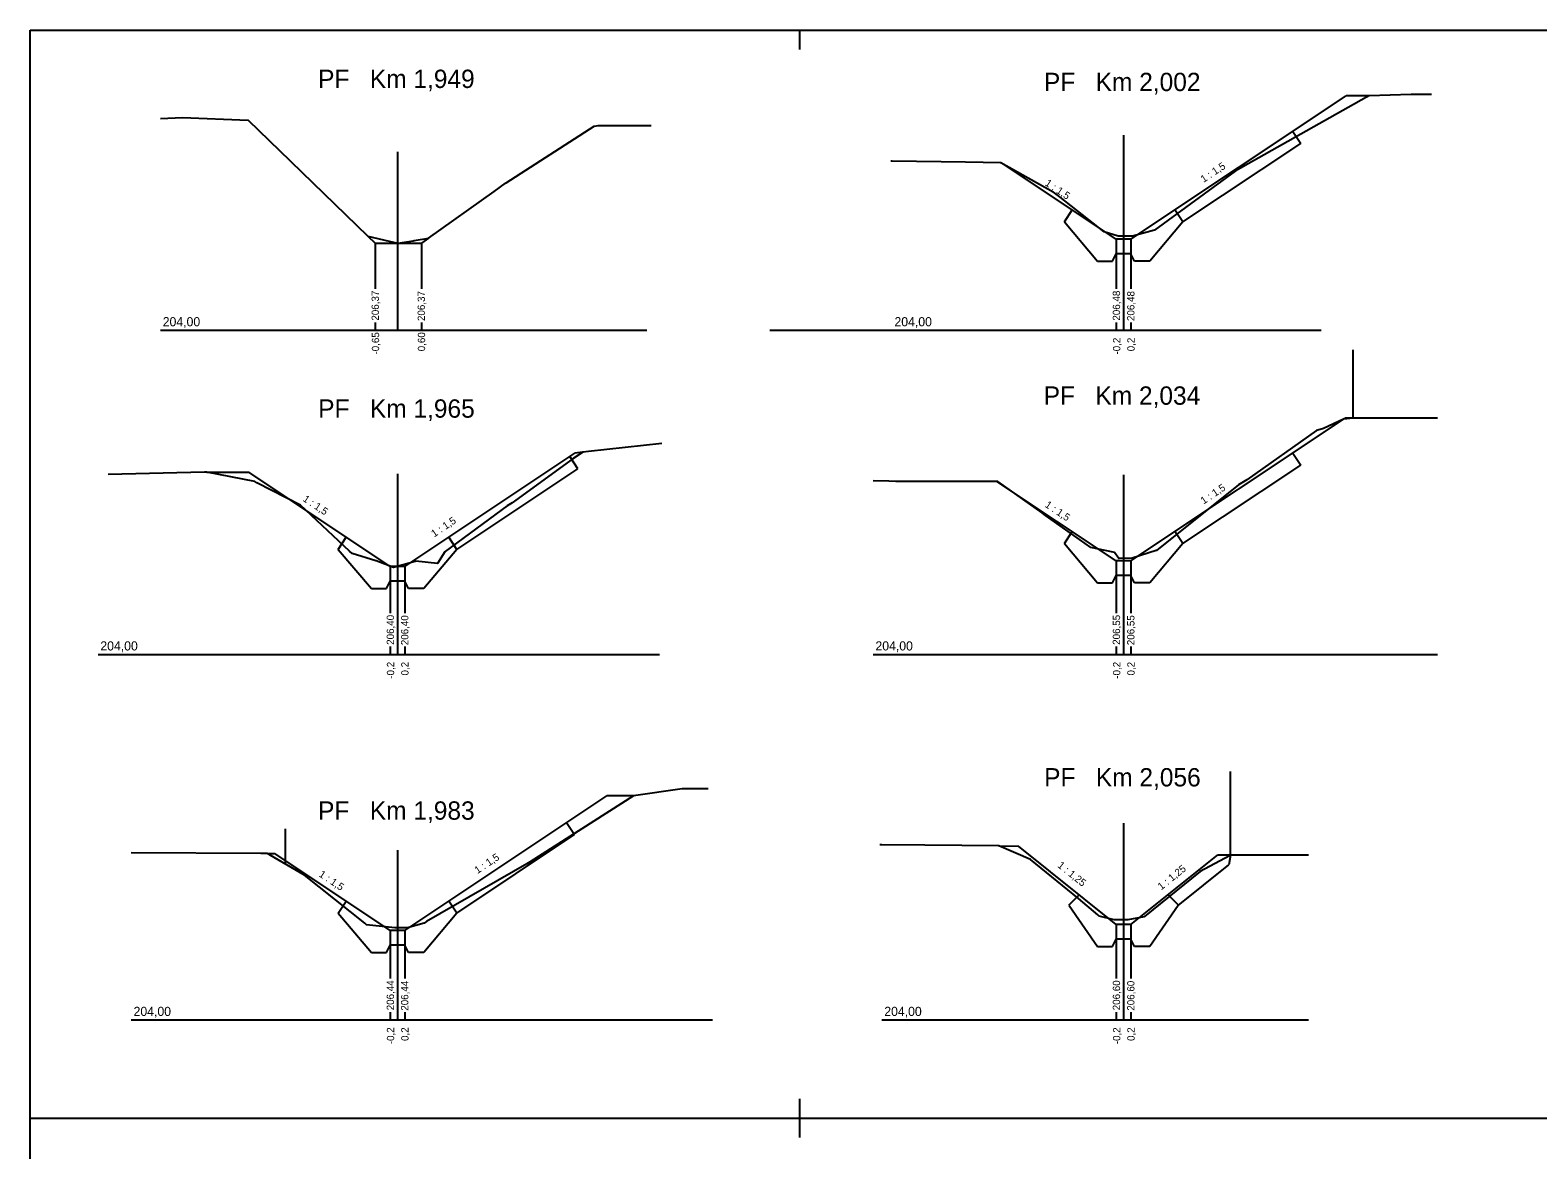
# Model space of a CAD drawing. Extents: x -547174 to -543113, y -1125006 to -1123643.
# Drawn here: x -547152.27 to -547111.11, y -1123875.1 to -1123844.54 of the extents above; entities that cross this region are included whole.
import ezdxf

# ---------------------------------------------------------------- set-up
doc = ezdxf.new("R2010")
doc.units = 0
for name, color, linetype in [('Default', 7, 'Continuous'), ('Profile', 7, 'Continuous'), ('PROFILY NÁVRH', 7, 'Continuous'), ('Section', 7, 'Continuous'), ('STANIČENÍ', 7, 'Continuous')]:
    doc.layers.add(name, color=color, linetype=linetype)

msp = doc.modelspace()

# ---------------------------------------------------------------- linework, layer by layer
at = {"layer": 'Default'}
for points in [[(-547114.012, -1123846.293), (-547114.571, -1123846.296), (-547114.574, -1123846.292), (-547115.721, -1123846.332), (-547115.75, -1123846.34), (-547115.752, -1123846.343), (-547115.789, -1123846.369), (-547119.372, -1123848.383), (-547121.574, -1123849.994), (-547121.578, -1123849.997), (-547122.174, -1123850.157), (-547122.175, -1123850.157), (-547122.416, -1123850.157), (-547122.416, -1123850.158), (-547122.417, -1123850.157), (-547122.573, -1123850.157), (-547122.574, -1123850.157), (-547122.574, -1123850.157), (-547122.952, -1123850.046), (-547124.157, -1123849.1), (-547124.337, -1123848.958), (-547124.339, -1123848.957), (-547124.34, -1123848.956), (-547125.777, -1123848.157), (-547126.739, -1123848.144), (-547128.74, -1123848.114), (-547128.776, -1123848.116)], [(-547148.717, -1123846.952), (-547148.117, -1123846.924), (-547146.32, -1123846.999), (-547145.178, -1123848.103), (-547145.175, -1123848.107), (-547145.168, -1123848.114), (-547143.058, -1123850.16), (-547142.47, -1123850.296), (-547142.467, -1123850.296), (-547142.238, -1123850.349), (-547142.236, -1123850.349), (-547141.82, -1123850.289), (-547141.788, -1123850.279), (-547141.396, -1123850.219), (-547139.605, -1123848.941), (-547139.291, -1123848.717), (-547139.277, -1123848.708), (-547136.874, -1123847.16), (-547136.77, -1123847.14), (-547135.32, -1123847.143)], [(-547113.853, -1123855.128), (-547114.6, -1123855.128), (-547116.156, -1123855.13), (-547116.418, -1123855.154), (-547116.963, -1123855.415), (-547116.988, -1123855.425), (-547117.151, -1123855.47), (-547117.152, -1123855.47), (-547119.059, -1123856.814), (-547119.197, -1123856.891), (-547119.282, -1123856.954), (-547121.519, -1123858.741), (-547121.536, -1123858.745), (-547122.189, -1123858.949), (-547122.197, -1123858.949), (-547122.542, -1123858.959), (-547122.548, -1123858.959), (-547122.67, -1123858.795), (-547122.705, -1123858.787), (-547123.312, -1123858.663), (-547124.553, -1123857.784), (-547124.587, -1123857.757), (-547124.641, -1123857.714), (-547125.859, -1123856.856), (-547125.859, -1123856.856), (-547125.984, -1123856.856), (-547128.337, -1123856.86), (-547128.338, -1123856.86), (-547128.639, -1123856.856), (-547128.831, -1123856.853), (-547129.259, -1123856.84)], [(-547135.025, -1123855.821), (-547137.03, -1123856.043), (-547137.182, -1123856.06), (-547137.451, -1123856.232), (-547139.111, -1123857.443), (-547139.246, -1123857.523), (-547140.942, -1123858.768), (-547140.954, -1123858.783), (-547141.151, -1123859.099), (-547141.74, -1123859.032), (-547141.765, -1123859.041), (-547142.349, -1123859.207), (-547142.352, -1123859.207), (-547142.355, -1123859.207), (-547142.829, -1123859.029), (-547142.836, -1123859.028), (-547143.48, -1123858.828), (-547143.481, -1123858.827), (-547143.553, -1123858.763), (-547144.893, -1123857.509), (-547146.084, -1123856.894), (-547146.141, -1123856.858), (-547147.452, -1123856.604), (-547147.509, -1123856.604), (-547150.146, -1123856.67)], [(-547133.762, -1123865.246), (-547134.072, -1123865.245), (-547134.465, -1123865.245), (-547134.467, -1123865.245), (-547134.47, -1123865.245), (-547135.799, -1123865.441), (-547138.626, -1123867.242), (-547138.717, -1123867.293), (-547141.456, -1123868.869), (-547141.516, -1123868.913), (-547141.968, -1123869.041), (-547141.978, -1123869.044), (-547141.983, -1123869.044), (-547142.14, -1123869.044), (-547142.308, -1123869.044), (-547142.311, -1123869.044), (-547142.319, -1123869.042), (-547143.086, -1123868.962), (-547143.139, -1123868.921), (-547144.781, -1123867.607), (-547145.717, -1123867.061), (-547145.801, -1123867.013), (-547145.979, -1123867.011), (-547149.513, -1123866.992)], [(-547117.373, -1123867.058), (-547119.462, -1123867.063), (-547119.505, -1123867.063), (-547119.528, -1123867.078), (-547120.332, -1123867.504), (-547121.851, -1123868.739), (-547121.859, -1123868.745), (-547121.861, -1123868.745), (-547122.306, -1123868.825), (-547122.504, -1123868.825), (-547122.506, -1123868.825), (-547122.508, -1123868.825), (-547122.673, -1123868.825), (-547122.677, -1123868.825), (-547123.084, -1123868.725), (-547123.129, -1123868.689), (-547123.655, -1123868.241), (-547124.96, -1123867.18), (-547125.826, -1123866.805), (-547127.849, -1123866.786), (-547129.019, -1123866.78), (-547129.077, -1123866.778)]]:
    msp.add_lwpolyline(points, dxfattribs=at)
at = {"layer": 'Profile'}
for p, q in [((-547152.272, -1123844.537), (-547131.272, -1123844.537)), ((-547152.272, -1123874.237), (-547152.272, -1123844.537)), ((-547131.272, -1123844.537), (-547110.272, -1123844.537)), ((-547131.272, -1123844.537), (-547131.272, -1123845.065)), ((-547131.272, -1123873.709), (-547131.272, -1123874.237)), ((-547152.272, -1123874.237), (-547138.818, -1123874.237)), ((-547152.272, -1123874.237), (-547131.272, -1123874.237)), ((-547152.272, -1123903.937), (-547152.272, -1123874.237)), ((-547131.272, -1123874.237), (-547115.303, -1123874.237)), ((-547131.272, -1123874.237), (-547110.272, -1123874.237)), ((-547131.272, -1123874.237), (-547131.272, -1123874.765))]:
    msp.add_line(p, q, dxfattribs=at)
at = {"layer": 'PROFILY NÁVRH'}
for p, q in [((-547122.221, -1123850.247), (-547116.348, -1123846.332)), ((-547115.721, -1123846.332), (-547116.348, -1123846.332)), ((-547117.804, -1123847.302), (-547117.586, -1123847.629)), ((-547120.803, -1123849.773), (-547117.586, -1123847.629)), ((-547125.777, -1123848.157), (-547125.755, -1123848.158)), ((-547122.621, -1123850.247), (-547125.755, -1123848.158)), ((-547124.038, -1123849.773), (-547123.821, -1123849.447)), ((-547120.803, -1123849.773), (-547121.021, -1123849.447)), ((-547124.038, -1123849.773), (-547123.136, -1123850.847)), ((-547120.803, -1123849.773), (-547121.706, -1123850.847)), ((-547143.058, -1123850.16), (-547142.854, -1123850.357)), ((-547141.396, -1123850.219), (-547141.59, -1123850.357)), ((-547122.221, -1123850.247), (-547122.621, -1123850.247)), ((-547122.621, -1123850.247), (-547122.621, -1123851.603)), ((-547122.221, -1123850.247), (-547122.221, -1123851.603)), ((-547142.854, -1123850.357), (-547141.59, -1123850.357)), ((-547142.854, -1123850.357), (-547142.854, -1123851.603)), ((-547141.59, -1123850.357), (-547141.59, -1123851.603)), ((-547122.721, -1123850.847), (-547122.621, -1123850.647)), ((-547122.221, -1123850.647), (-547122.621, -1123850.647)), ((-547122.121, -1123850.847), (-547122.221, -1123850.647)), ((-547123.136, -1123850.847), (-547122.721, -1123850.847)), ((-547121.706, -1123850.847), (-547122.121, -1123850.847)), ((-547142.854, -1123852.515), (-547142.854, -1123852.727)), ((-547141.59, -1123852.515), (-547141.59, -1123852.727)), ((-547122.621, -1123852.515), (-547122.621, -1123852.727)), ((-547122.221, -1123852.515), (-547122.221, -1123852.727)), ((-547122.221, -1123859.028), (-547116.374, -1123855.13)), ((-547116.156, -1123855.13), (-547116.374, -1123855.13)), ((-547142.043, -1123859.178), (-547137.404, -1123856.085)), ((-547137.182, -1123856.06), (-547137.404, -1123856.085)), ((-547117.804, -1123856.083), (-547117.586, -1123856.409)), ((-547140.621, -1123858.711), (-547137.321, -1123856.511)), ((-547137.321, -1123856.511), (-547137.543, -1123856.178)), ((-547120.803, -1123858.554), (-547117.586, -1123856.409)), ((-547147.452, -1123856.604), (-547146.303, -1123856.604)), ((-547142.443, -1123859.178), (-547146.303, -1123856.604)), ((-547122.621, -1123859.028), (-547125.878, -1123856.856)), ((-547143.865, -1123858.711), (-547143.643, -1123858.378)), ((-547140.621, -1123858.711), (-547140.843, -1123858.378)), ((-547124.038, -1123858.554), (-547123.821, -1123858.228)), ((-547124.038, -1123858.554), (-547123.136, -1123859.628)), ((-547120.803, -1123858.554), (-547121.706, -1123859.628)), ((-547120.803, -1123858.554), (-547121.021, -1123858.228)), ((-547143.865, -1123858.711), (-547142.958, -1123859.778)), ((-547140.621, -1123858.711), (-547141.528, -1123859.778)), ((-547142.043, -1123859.178), (-547142.443, -1123859.178)), ((-547142.443, -1123859.178), (-547142.443, -1123860.454)), ((-547142.043, -1123859.178), (-547142.043, -1123860.454)), ((-547122.221, -1123859.028), (-547122.621, -1123859.028)), ((-547122.621, -1123859.028), (-547122.621, -1123860.454)), ((-547122.221, -1123859.028), (-547122.221, -1123860.454)), ((-547142.958, -1123859.778), (-547142.543, -1123859.778)), ((-547142.543, -1123859.778), (-547142.443, -1123859.578)), ((-547142.043, -1123859.578), (-547142.443, -1123859.578)), ((-547141.943, -1123859.778), (-547142.043, -1123859.578)), ((-547141.528, -1123859.778), (-547141.943, -1123859.778)), ((-547123.136, -1123859.628), (-547122.721, -1123859.628)), ((-547122.721, -1123859.628), (-547122.621, -1123859.428)), ((-547122.221, -1123859.428), (-547122.621, -1123859.428)), ((-547122.121, -1123859.628), (-547122.221, -1123859.428)), ((-547121.706, -1123859.628), (-547122.121, -1123859.628)), ((-547142.443, -1123861.366), (-547142.443, -1123861.578)), ((-547142.043, -1123861.366), (-547142.043, -1123861.578)), ((-547122.621, -1123861.366), (-547122.621, -1123861.578)), ((-547122.221, -1123861.366), (-547122.221, -1123861.578)), ((-547142.043, -1123869.115), (-547136.531, -1123865.441)), ((-547135.799, -1123865.441), (-547136.531, -1123865.441)), ((-547145.313, -1123866.345), (-547145.313, -1123867.296)), ((-547137.626, -1123866.171), (-547137.408, -1123866.497)), ((-547140.625, -1123868.642), (-547137.408, -1123866.497)), ((-547145.801, -1123867.013), (-547145.591, -1123867.016)), ((-547142.443, -1123869.115), (-547145.591, -1123867.016)), ((-547125.826, -1123866.805), (-547125.295, -1123866.81)), ((-547122.621, -1123868.955), (-547125.295, -1123866.81)), ((-547122.221, -1123868.955), (-547119.862, -1123867.063)), ((-547119.505, -1123867.063), (-547119.862, -1123867.063)), ((-547119.505, -1123867.063), (-547119.552, -1123867.327)), ((-547120.931, -1123868.433), (-547119.552, -1123867.327)), ((-547143.86, -1123868.642), (-547143.643, -1123868.315)), ((-547140.625, -1123868.642), (-547140.843, -1123868.315)), ((-547123.915, -1123868.426), (-547123.633, -1123868.143)), ((-547123.911, -1123868.433), (-547123.136, -1123869.555)), ((-547120.931, -1123868.433), (-547121.706, -1123869.555)), ((-547120.926, -1123868.426), (-547121.209, -1123868.143)), ((-547143.86, -1123868.642), (-547142.958, -1123869.715)), ((-547140.625, -1123868.642), (-547141.528, -1123869.715)), ((-547142.043, -1123869.115), (-547142.443, -1123869.115)), ((-547142.443, -1123869.115), (-547142.443, -1123870.431)), ((-547142.043, -1123869.115), (-547142.043, -1123870.431)), ((-547122.221, -1123868.955), (-547122.621, -1123868.955)), ((-547122.221, -1123868.955), (-547122.621, -1123868.955)), ((-547122.621, -1123868.955), (-547122.621, -1123870.431)), ((-547122.221, -1123868.955), (-547122.221, -1123870.431)), ((-547142.543, -1123869.715), (-547142.443, -1123869.515)), ((-547142.043, -1123869.515), (-547142.443, -1123869.515)), ((-547141.943, -1123869.715), (-547142.043, -1123869.515)), ((-547123.136, -1123869.555), (-547122.721, -1123869.555)), ((-547122.721, -1123869.555), (-547122.621, -1123869.355)), ((-547122.221, -1123869.355), (-547122.621, -1123869.355)), ((-547122.121, -1123869.555), (-547122.221, -1123869.355)), ((-547121.706, -1123869.555), (-547122.121, -1123869.555)), ((-547142.958, -1123869.715), (-547142.543, -1123869.715)), ((-547141.528, -1123869.715), (-547141.943, -1123869.715)), ((-547142.443, -1123871.343), (-547142.443, -1123871.555)), ((-547142.043, -1123871.343), (-547142.043, -1123871.555)), ((-547122.621, -1123871.343), (-547122.621, -1123871.555)), ((-547122.221, -1123871.343), (-547122.221, -1123871.555))]:
    msp.add_line(p, q, dxfattribs=at)
at = {"layer": 'Section'}
for p, q in [((-547122.421, -1123847.401), (-547122.421, -1123852.727)), ((-547142.243, -1123847.855), (-547142.243, -1123852.727)), ((-547148.717, -1123852.727), (-547135.436, -1123852.727)), ((-547132.078, -1123852.727), (-547117.031, -1123852.727)), ((-547142.243, -1123856.649), (-547142.243, -1123861.578)), ((-547122.421, -1123856.679), (-547122.421, -1123861.578)), ((-547150.42, -1123861.578), (-547135.091, -1123861.578)), ((-547129.259, -1123861.578), (-547113.853, -1123861.578)), ((-547122.421, -1123866.189), (-547122.421, -1123871.555)), ((-547142.243, -1123866.922), (-547142.243, -1123871.555)), ((-547149.513, -1123871.555), (-547133.643, -1123871.555)), ((-547129.019, -1123871.555), (-547117.373, -1123871.555))]:
    msp.add_line(p, q, dxfattribs=at)
at = {"layer": 'STANIČENÍ'}
for p, q in [((-547116.156, -1123855.13), (-547116.156, -1123853.26)), ((-547119.505, -1123867.063), (-547119.505, -1123864.772))]:
    msp.add_line(p, q, dxfattribs=at)

# ---------------------------------------------------------------- texts
at = {"layer": 'PROFILY NÁVRH'}
for s, rotation, p in [('1 : 1,5', 33.6901, (-547120.237, -1123848.708)), ('1 : 1,5', 326.3099, (-547124.586, -1123848.76)), ('206,37', 90, (-547142.751, -1123852.467)), ('206,37', 90, (-547141.495, -1123852.478)), ('206,48', 90, (-547122.517, -1123852.467)), ('206,48', 90, (-547122.125, -1123852.478)), ('-0,65', 90, (-547142.745, -1123853.393)), ('0,60', 90, (-547141.489, -1123853.304)), ('-0,2', 90, (-547122.511, -1123853.393)), ('0,2', 90, (-547122.12, -1123853.304)), ('1 : 1,5', 33.6901, (-547120.237, -1123857.488)), ('1 : 1,5', 326.3099, (-547144.845, -1123857.378)), ('1 : 1,5', 326.3099, (-547124.586, -1123857.54)), ('1 : 1,5', 33.6901, (-547141.242, -1123858.388)), ('206,40', 90, (-547142.339, -1123861.318)), ('206,40', 90, (-547141.948, -1123861.328)), ('206,55', 90, (-547122.517, -1123861.318)), ('206,55', 90, (-547122.125, -1123861.328)), ('-0,2', 90, (-547142.334, -1123862.243)), ('0,2', 90, (-547141.942, -1123862.155)), ('-0,2', 90, (-547122.511, -1123862.243)), ('0,2', 90, (-547122.12, -1123862.155)), ('1 : 1,5', 33.6901, (-547140.06, -1123867.576)), ('1 : 1,5', 326.3099, (-547144.408, -1123867.628)), ('1 : 1,25', 321.2587, (-547124.241, -1123867.371)), ('1 : 1,25', 38.7413, (-547121.393, -1123868.023)), ('206,44', 90, (-547142.339, -1123871.295)), ('206,44', 90, (-547141.948, -1123871.306)), ('206,60', 90, (-547122.517, -1123871.295)), ('206,60', 90, (-547122.125, -1123871.306)), ('-0,2', 90, (-547142.334, -1123872.221)), ('0,2', 90, (-547141.942, -1123872.132)), ('-0,2', 90, (-547122.511, -1123872.221)), ('0,2', 90, (-547122.12, -1123872.132))]:
    msp.add_text(s, height=0.2, rotation=rotation, dxfattribs=at).set_placement(p)
at = {"layer": 'Section'}
for s, height, p in [('PF   Km 1,949', 0.5, (-547144.41, -1123846.116)), ('PF   Km 2,002', 0.5, (-547124.596, -1123846.201)), ('204,00', 0.25, (-547148.653, -1123852.622)), ('204,00', 0.25, (-547128.677, -1123852.622)), ('PF   Km 2,034', 0.5, (-547124.602, -1123854.763)), ('PF   Km 1,965', 0.5, (-547144.409, -1123855.117)), ('204,00', 0.25, (-547150.356, -1123861.472)), ('204,00', 0.25, (-547129.196, -1123861.472)), ('PF   Km 2,056', 0.5, (-547124.59, -1123865.184)), ('PF   Km 1,983', 0.5, (-547144.411, -1123866.092)), ('204,00', 0.25, (-547149.449, -1123871.45)), ('204,00', 0.25, (-547128.955, -1123871.45))]:
    msp.add_text(s, height=height, dxfattribs=at).set_placement(p)

doc.saveas('drawing.dxf')
